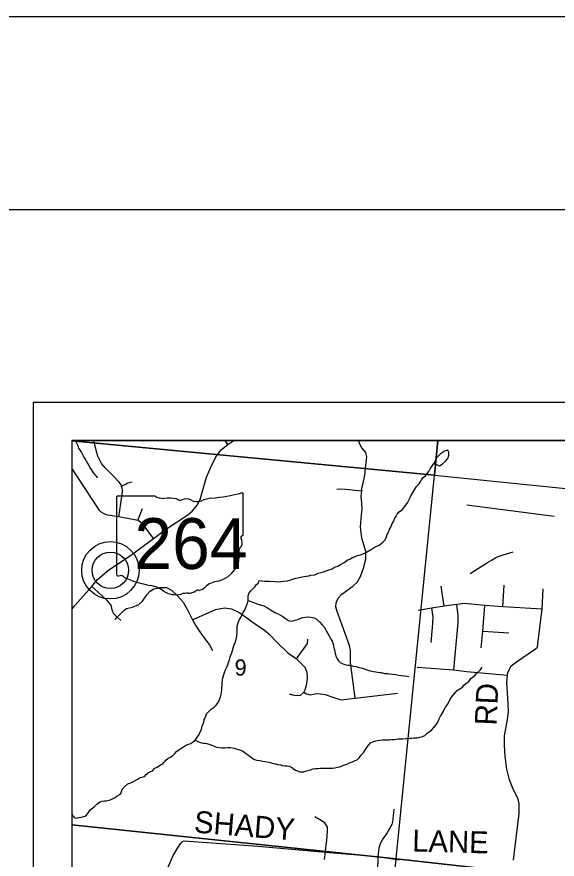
# Model space of a CAD drawing. Extents: x 0 to 43.4, y -8.1 to 22.
# Drawn here: x 1.957 to 3.361, y 19.813 to 22 of the extents above; entities that cross this region are included whole.
import ezdxf

# ---------------------------------------------------------------- set-up
doc = ezdxf.new("R2010")
doc.units = 0
for name, color, linetype in [('GM_X_Corporation', 7, 'Continuous'), ('GM_X_County_Road', 7, 'Continuous'), ('GM_X_County_Road_Text', 7, 'Continuous'), ('GM_X_Minor_Lake', 7, 'Continuous'), ('GM_X_Minor_River', 7, 'Continuous'), ('GM_X_Section_Text', 7, 'Continuous'), ('GM_X_State_Location', 7, 'Continuous'), ('GM_X_State_Route', 7, 'Continuous'), ('GM_X_State_Shield', 7, 'Continuous'), ('GM_X_Township_Road', 7, 'Continuous'), ('GM_X_Unincorporated', 7, 'Continuous'), ('GM_X_Unincorporated_Location', 7, 'Continuous'), ('SH_Border', 7, 'Continuous'), ('SH_Cut_Line', 7, 'Continuous'), ('SH_Data', 7, 'Continuous')]:
    doc.layers.add(name, color=color, linetype=linetype)

msp = doc.modelspace()

# ---------------------------------------------------------------- linework, layer by layer
at = {"layer": 'GM_X_Corporation'}
for points in [[(8.9, 20.9), (2.1, 20.9), (2.1, 18.7697), (2.2164, 18.6602), (2.3024, 18.5637), (2.4531, 18.3722), (2.5091, 18.2757), (2.5944, 18.1569), (2.6477, 18.0826), (2.8129, 17.7895), (2.9482, 17.5993), (3.2529, 17.1207), (3.3535, 16.9292), (3.4766, 16.7366), (3.5579, 16.6418), (3.619, 16.5459), (3.7774, 16.2543), (3.8686, 16.1561), (3.9643, 16.0791), (4.2564, 15.9373), (4.3533, 15.9108)], [(3.918, 19.4441), (3.9936, 20.1953), (4.0006, 20.2658), (4.0111, 20.3696), (4.0645, 20.9), (2.1, 20.9), (2.1, 18.7697)]]:
    msp.add_lwpolyline(points, dxfattribs=at)
for points in [[(3.0509, 20.9), (2.1, 20.9), (2.1, 20.8994), (3.042, 20.8098)], [(2.1, 20.8994), (2.1, 19.9021), (2.9428, 19.8144), (3.042, 20.8098)], [(4.0674, 20.9), (3.0509, 20.9), (3.042, 20.8098), (4.0476, 20.7082)], [(4.0476, 20.7082), (3.9403, 19.703), (2.9428, 19.8144), (3.042, 20.8098)], [(2.1, 19.9021), (2.1, 18.897), (2.8429, 18.8166), (2.9428, 19.8144)], [(2.9428, 19.8144), (3.9403, 19.703), (3.8378, 18.6959), (2.8429, 18.8166)]]:
    msp.add_lwpolyline(points, close=True, dxfattribs=at)
at = {"layer": 'GM_X_County_Road'}
for points in [[(3.2479, 19.8108), (3.2621, 19.9316), (3.2624, 19.9576), (3.2602, 19.9693), (3.245, 19.9994), (3.237, 20.0194), (3.2307, 20.0466), (3.226, 20.0798), (3.2241, 20.1093), (3.224, 20.1332), (3.2284, 20.1566), (3.2324, 20.1755), (3.2344, 20.1964), (3.2335, 20.2158), (3.2317, 20.2451), (3.2301, 20.2706), (3.2314, 20.282), (3.2322, 20.2908), (3.2333, 20.2971), (3.2362, 20.3051), (3.242, 20.315), (3.2554, 20.3258), (3.3049, 20.3594), (3.31, 20.3635), (3.3119, 20.3801), (3.3218, 20.4625), (3.3246, 20.515)], [(2.3455, 19.7799), (2.363, 19.8224), (2.3734, 19.8403), (2.3829, 19.8545), (2.3872, 19.859), (2.3922, 19.8611), (2.5831, 19.8466), (2.759, 19.8311), (2.8955, 19.8202), (2.9503, 19.8114)]]:
    msp.add_lwpolyline(points, dxfattribs=at)
at = {"layer": 'GM_X_Minor_Lake'}
for points in [[(3.041, 20.84), (3.0558, 20.8343), (3.0624, 20.8387), (3.071, 20.8464), (3.0773, 20.8535), (3.0798, 20.8621), (3.0796, 20.8694), (3.0771, 20.8751), (3.0686, 20.8723), (3.0578, 20.8654), (3.0492, 20.8572)], [(3.0492, 20.8572), (3.0457, 20.8532), (3.0432, 20.8445), (3.041, 20.84)]]:
    msp.add_lwpolyline(points, dxfattribs=at)
at = {"layer": 'GM_X_Minor_River'}
for points in [[(2.1089, 20.9), (2.1124, 20.8942), (2.1155, 20.8869), (2.1176, 20.8803), (2.1216, 20.8741), (2.1252, 20.8687), (2.1277, 20.8636), (2.1312, 20.8567), (2.1348, 20.8516), (2.138, 20.8454), (2.1413, 20.8396), (2.1441, 20.8349), (2.1488, 20.8272), (2.1575, 20.8147), (2.1615, 20.8096), (2.1655, 20.8038), (2.1661, 20.8028)], [(2.6008, 20.5352), (2.6053, 20.5347), (2.6133, 20.5348), (2.6273, 20.5343), (2.6383, 20.5335), (2.6429, 20.5338), (2.6501, 20.5347), (2.6604, 20.5362), (2.6669, 20.5375), (2.6742, 20.5399), (2.6819, 20.5427), (2.6869, 20.5436), (2.6987, 20.5459), (2.704, 20.5469), (2.7094, 20.5478), (2.7159, 20.5491), (2.7209, 20.5504), (2.7312, 20.5516), (2.7404, 20.5555), (2.7481, 20.5571), (2.7592, 20.5613), (2.7654, 20.5637), (2.7761, 20.5672), (2.7846, 20.5722), (2.7908, 20.5739), (2.7978, 20.5778), (2.8094, 20.5843), (2.816, 20.5901), (2.821, 20.5914), (2.8295, 20.5961), (2.8341, 20.5982), (2.8399, 20.6011), (2.8457, 20.6028), (2.8529, 20.604), (2.8591, 20.6068), (2.8653, 20.6104), (2.87, 20.6129), (2.8808, 20.6186), (2.8855, 20.6223), (2.8909, 20.6251), (2.8982, 20.6283), (2.9029, 20.6316), (2.9087, 20.6367), (2.9146, 20.6422), (2.9179, 20.65), (2.9196, 20.6557), (2.9217, 20.6605), (2.9242, 20.6654), (2.9258, 20.6699), (2.9287, 20.6751), (2.9303, 20.6796), (2.9324, 20.6849), (2.9356, 20.6897), (2.9377, 20.6942), (2.9393, 20.6987), (2.9425, 20.7035), (2.9458, 20.7087), (2.9505, 20.715), (2.9595, 20.7212), (2.9643, 20.7279), (2.9682, 20.7323), (2.9718, 20.7379), (2.9747, 20.7431), (2.9788, 20.7521), (2.9816, 20.758), (2.9864, 20.7651), (2.9909, 20.7741), (2.9953, 20.7804), (3.0024, 20.7873), (3.0052, 20.7918), (3.0084, 20.7978), (3.0132, 20.8037), (3.0194, 20.8084), (3.0227, 20.814), (3.0278, 20.8199), (3.0314, 20.8262), (3.0371, 20.8355), (3.041, 20.84)], [(2.5294, 20.413), (2.5295, 20.4184), (2.5312, 20.424), (2.5333, 20.4292), (2.5358, 20.4352), (2.5399, 20.4423), (2.5424, 20.4487), (2.5456, 20.4539), (2.5484, 20.4591), (2.5521, 20.4662), (2.5546, 20.4734), (2.5575, 20.4801), (2.558, 20.4846), (2.5579, 20.4915), (2.5584, 20.4972), (2.561, 20.5043), (2.5658, 20.511), (2.5716, 20.5157), (2.576, 20.5209), (2.5788, 20.5253), (2.5846, 20.5301), (2.5872, 20.5368), (2.6008, 20.5352)], [(2.558, 20.485), (2.573, 20.4792), (2.5775, 20.4779), (2.5835, 20.475), (2.5925, 20.4728), (2.5985, 20.4707), (2.6086, 20.4658), (2.6164, 20.4606), (2.625, 20.455), (2.6294, 20.4529), (2.6358, 20.45), (2.6485, 20.4435), (2.6551, 20.4383), (2.6633, 20.4331), (2.6701, 20.431), (2.6754, 20.4315), (2.6804, 20.4337), (2.6869, 20.4353), (2.6923, 20.4378), (2.7004, 20.4402), (2.7076, 20.4418), (2.7156, 20.4419), (2.7254, 20.4405), (2.73, 20.4399), (2.7355, 20.4363), (2.7444, 20.4288), (2.7502, 20.4217), (2.7572, 20.4143), (2.7589, 20.4097), (2.7614, 20.4042), (2.7661, 20.3969), (2.77, 20.3891), (2.7732, 20.3845), (2.7761, 20.379), (2.7789, 20.3721), (2.7798, 20.3664), (2.7808, 20.3614), (2.7835, 20.3529), (2.7845, 20.3468), (2.7868, 20.3384), (2.7893, 20.3333), (2.7926, 20.3283), (2.7973, 20.3236), (2.8026, 20.3215), (2.8071, 20.3198), (2.8116, 20.3181), (2.8169, 20.3172), (2.8229, 20.3166), (2.8286, 20.3153), (2.8331, 20.3143), (2.8391, 20.313), (2.8436, 20.3117), (2.8508, 20.3096), (2.8606, 20.3073), (2.8658, 20.3049), (2.8748, 20.3023), (2.8797, 20.3009), (2.8842, 20.3), (2.8899, 20.2991), (2.8982, 20.298), (2.9035, 20.2975), (2.9125, 20.2956), (2.9209, 20.295), (2.9258, 20.294), (2.933, 20.2934), (2.9409, 20.2924), (2.9492, 20.2913), (2.9564, 20.2899), (2.9647, 20.2889), (2.9711, 20.2879), (2.976, 20.2874)], [(2.1, 19.9302), (2.1029, 19.9257), (2.1073, 19.9206), (2.1125, 19.9197), (2.1175, 19.9214), (2.1236, 19.9223), (2.129, 19.9229), (2.1336, 19.9247), (2.1383, 19.9275), (2.1431, 19.9346), (2.1478, 19.9413), (2.158, 19.9489), (2.1643, 19.9555), (2.169, 19.9592), (2.1736, 19.962), (2.1786, 19.9634), (2.1847, 19.9643), (2.19, 19.9649), (2.1977, 19.9662), (2.2038, 19.969), (2.2127, 19.9732), (2.2174, 19.9765), (2.2225, 19.9801), (2.2271, 19.9838), (2.2288, 19.9886), (2.2317, 19.9961), (2.2372, 20.0013), (2.2455, 20.0086), (2.2508, 20.0107), (2.2582, 20.0142), (2.2648, 20.0178), (2.2713, 20.0206), (2.276, 20.0246), (2.2886, 20.028), (2.293, 20.0332), (2.2988, 20.0371), (2.3054, 20.0411), (2.31, 20.0428), (2.316, 20.0491), (2.3214, 20.0523), (2.3307, 20.0581), (2.3365, 20.0606), (2.3444, 20.0698), (2.3495, 20.0742), (2.3564, 20.0781), (2.3631, 20.0836), (2.3681, 20.0872), (2.3721, 20.0924), (2.3834, 20.1004), (2.3904, 20.1051), (2.3978, 20.1097), (2.4032, 20.1118), (2.4093, 20.1135), (2.414, 20.1172), (2.4186, 20.12), (2.4234, 20.1252), (2.4266, 20.1308), (2.431, 20.1371), (2.4339, 20.1438), (2.4368, 20.1502), (2.4389, 20.1585), (2.4411, 20.1649), (2.4427, 20.1698), (2.4437, 20.1754), (2.4461, 20.1799), (2.4478, 20.1844), (2.4503, 20.1908), (2.457, 20.1974), (2.4621, 20.2025), (2.4699, 20.208), (2.4754, 20.2131), (2.4789, 20.2175), (2.4822, 20.2235), (2.4839, 20.228), (2.4864, 20.2344), (2.489, 20.2449), (2.4897, 20.2536), (2.4899, 20.2586), (2.4904, 20.2646), (2.491, 20.2707), (2.4916, 20.2771), (2.4926, 20.2843), (2.4944, 20.2904), (2.4969, 20.2982), (2.4994, 20.305), (2.5031, 20.3117), (2.5052, 20.3181), (2.5073, 20.3237), (2.5094, 20.3305), (2.5112, 20.3373), (2.5136, 20.3425), (2.5157, 20.3485), (2.5179, 20.3553), (2.5213, 20.3666), (2.5263, 20.3801), (2.529, 20.3922), (2.5294, 20.4047), (2.5294, 20.413)], [(3.076, 20.2147), (3.0793, 20.2211), (3.0825, 20.227), (3.0862, 20.2334), (3.0897, 20.2378), (3.0953, 20.2441), (3.1016, 20.2507), (3.1082, 20.2558), (3.1155, 20.2597), (3.1188, 20.2646), (3.1238, 20.2689), (3.1312, 20.2744), (3.1368, 20.2818), (3.147, 20.2902), (3.1529, 20.2972), (3.1607, 20.3041), (3.1666, 20.3118)], [(2.4207, 20.1223), (2.4292, 20.1182), (2.4341, 20.1161), (2.4401, 20.1147), (2.4465, 20.1141), (2.451, 20.1132), (2.4559, 20.1115), (2.4638, 20.109), (2.4713, 20.1057), (2.4758, 20.104), (2.4837, 20.103), (2.4902, 20.1024), (2.4974, 20.1025), (2.5054, 20.103), (2.5122, 20.1031), (2.5216, 20.1013), (2.5269, 20.0999), (2.5333, 20.0978), (2.5438, 20.094), (2.5512, 20.0885), (2.5564, 20.0852), (2.5638, 20.0793), (2.5701, 20.0749), (2.5745, 20.0721), (2.5809, 20.0703), (2.5873, 20.069), (2.596, 20.0679), (2.6013, 20.0666), (2.6066, 20.0656), (2.6122, 20.0647), (2.6205, 20.0625), (2.6299, 20.0603), (2.6352, 20.0589), (2.642, 20.058), (2.6477, 20.0566), (2.6544, 20.0556), (2.6594, 20.0551), (2.6639, 20.0549), (2.671, 20.0516), (2.6755, 20.0488), (2.6814, 20.044), (2.6923, 20.0402), (2.6968, 20.0397), (2.7025, 20.0403), (2.7075, 20.042), (2.7205, 20.045), (2.7274, 20.0474), (2.7332, 20.0483), (2.7389, 20.0489), (2.7457, 20.0494), (2.7548, 20.0491), (2.7704, 20.0493), (2.7772, 20.0495), (2.7833, 20.0504), (2.7902, 20.0517), (2.799, 20.054), (2.8056, 20.0572), (2.8152, 20.0599), (2.8218, 20.0635), (2.8294, 20.0659), (2.8341, 20.0684), (2.8426, 20.0719), (2.8469, 20.0763), (2.8509, 20.0823), (2.8588, 20.0907), (2.866, 20.1019), (2.8716, 20.1104), (2.8763, 20.1152), (2.884, 20.1184), (2.8902, 20.1208), (2.9005, 20.1224), (2.9073, 20.1229), (2.9134, 20.123), (2.9256, 20.123), (2.9305, 20.1236), (2.9381, 20.1241), (2.9427, 20.1247), (2.9477, 20.1253), (2.9537, 20.1255), (2.9602, 20.1256), (2.9682, 20.1265), (2.9728, 20.1267), (2.9781, 20.1269), (2.9838, 20.1275), (2.9888, 20.128), (2.9979, 20.1285), (3.004, 20.1298), (3.0113, 20.1318), (3.0174, 20.1339), (3.0226, 20.1394), (3.0354, 20.1492), (3.0398, 20.1544), (3.0453, 20.1599), (3.0505, 20.1673), (3.0542, 20.1775), (3.0579, 20.1846), (3.0627, 20.1912), (3.0648, 20.1961), (3.0676, 20.2013), (3.0709, 20.2081), (3.076, 20.2147)]]:
    msp.add_lwpolyline(points, dxfattribs=at)
at = {"layer": 'GM_X_State_Route'}
msp.add_lwpolyline([(2.1, 20.4615), (2.1077, 20.4715), (2.1522, 20.5213), (2.1669, 20.539), (2.1962, 20.5641), (2.2522, 20.6012), (2.3124, 20.6454), (2.3433, 20.6687), (2.4012, 20.7075), (2.4129, 20.7167), (2.419, 20.7235), (2.426, 20.7326), (2.4331, 20.7466), (2.4376, 20.7626), (2.45, 20.8048), (2.4624, 20.833), (2.4741, 20.8577), (2.4887, 20.8764), (2.5056, 20.8897), (2.5213, 20.9)], dxfattribs=at)
at = {"layer": 'GM_X_State_Shield'}
for p, q in [((2.3157, 20.756), (2.2192, 20.756)), ((2.5455, 20.6563), (2.5455, 20.761)), ((2.216, 20.7526), (2.216, 20.5525)), ((2.5455, 20.6563), (2.5455, 20.6563))]:
    msp.add_line(p, q, dxfattribs=at)
for centre, major_axis, start_param, end_param in [((2.2197, 20.753), (0.00382, 0), 1.712693, 3.28349), ((2.3387, 20.7793), (0.037, 0), 4.042523, 4.731795), ((2.4281, 21.0289), (0.3495, 0), 4.814394, 5.042369), ((2.5419, 20.7614), (0.00367, 0), 6.141152, 7.989035), ((2.351, 20.6437), (0.133, 0), 1.404758, 1.657858), ((2.3812, 20.754), (0.0107, 0), 3.836095, 5.185415), ((2.3968, 20.7309), (0.0222, 0), 0.950623, 2.079405), ((2.4255, 20.7626), (0.0267, 0), 4.081561, 5.145723), ((2.4727, 20.6949), (0.0703, 0), 1.699011, 2.107814), ((2.5447, 20.6486), (0.00568, 0), 1.883978, 3.671073), ((2.5086, 20.6354), (0.0341, 0), 5.934695, 6.695948), ((2.5416, 20.6559), (0.00393, 0), 5.05454, 6.418171), ((2.5587, 20.6125), (0.0248, 0), 2.387724, 3.262537), ((2.4477, 20.5992), (0.0874, 0), 5.101752, 6.440018), ((2.2198, 20.552), (0.00385, 0), 3.00124, 4.508301), ((2.2203, 20.5725), (0.0294, 0), 4.665946, 4.897461), ((2.2264, 20.5409), (0.0106, 0), 0.519207, 1.627899), ((2.3602, 20.7207), (0.2524, 0), 4.195997, 4.488961), ((2.4846, 20.4963), (0.0479, 0), 1.647645, 2.488434), ((2.2849, 20.4626), (0.079, 0), 0.823519, 1.323587), ((2.4239, 20.5331), (0.0282, 0), 4.937069, 5.64225), ((2.3703, 20.5399), (0.0501, 0), 4.026481, 4.996735), ((2.3993, 20.4707), (0.0412, 0), 1.495662, 1.94098), ((2.403, 20.5249), (0.0267, 0), 4.691044, 5.507374), ((2.4271, 20.5056), (0.00752, 0), 1.147584, 2.315152)]:
    msp.add_ellipse(centre, major_axis=major_axis, ratio=0.8, start_param=start_param, end_param=end_param, dxfattribs=at)
at = {"layer": 'GM_X_Township_Road'}
for p, q in [((2.5056, 20.8897), (2.4987, 20.9)), ((3.3535, 20.7029), (3.1266, 20.7322)), ((2.2719, 20.692), (2.284, 20.7235)), ((3.0672, 20.4702), (3.0596, 20.5216)), ((3.2196, 20.4687), (3.223, 20.5248)), ((3.1683, 20.4055), (3.2358, 20.4011))]:
    msp.add_line(p, q, dxfattribs=at)
for points in [[(2.2291, 20.7819), (2.2283, 20.7846), (2.226, 20.7885), (2.2219, 20.7929), (2.2083, 20.8073), (2.195, 20.8205), (2.1867, 20.8292), (2.1811, 20.8351), (2.1772, 20.8405), (2.1745, 20.8457), (2.1707, 20.8524), (2.1678, 20.8596), (2.1636, 20.8746), (2.1569, 20.9)], [(2.8362, 20.2313), (2.8239, 20.3239), (2.8239, 20.3402), (2.8239, 20.3539), (2.8218, 20.3676), (2.7989, 20.4306), (2.7892, 20.4561), (2.7859, 20.4679), (2.7868, 20.4783), (2.7918, 20.4908), (2.8017, 20.5008), (2.83, 20.5218), (2.8423, 20.5333), (2.8504, 20.5468), (2.8579, 20.5688), (2.8638, 20.5922), (2.8636, 20.6115), (2.8593, 20.6269), (2.8539, 20.6469), (2.8518, 20.6604), (2.8504, 20.6758), (2.8529, 20.7074), (2.8544, 20.7211), (2.8539, 20.7374), (2.8518, 20.7556), (2.8532, 20.7693), (2.8539, 20.7761), (2.8574, 20.7894), (2.8615, 20.8099), (2.8631, 20.8288), (2.8652, 20.8425), (2.8657, 20.8503), (2.8664, 20.8571), (2.8638, 20.8687), (2.8532, 20.8812), (2.847, 20.8937), (2.8463, 20.9)], [(2.3124, 20.6454), (2.2876, 20.679), (2.2831, 20.6843), (2.2788, 20.6878), (2.2749, 20.6907), (2.2719, 20.692), (2.2674, 20.6936), (2.2218, 20.7018), (2.1934, 20.7063), (2.1875, 20.7082), (2.182, 20.7106), (2.1764, 20.7143), (2.1721, 20.7183), (2.1674, 20.7252), (2.1, 20.8286)], [(2.2218, 20.7018), (2.2275, 20.7366), (2.2291, 20.7485), (2.2311, 20.7612), (2.2317, 20.7671), (2.2315, 20.772), (2.2309, 20.7756), (2.2295, 20.7803), (2.2291, 20.7819)], [(2.2291, 20.7819), (2.2358, 20.785), (2.2409, 20.7877), (2.2456, 20.79), (2.2487, 20.7913), (2.2521, 20.7922), (2.2568, 20.7929)], [(2.7887, 20.7741), (2.797, 20.7744), (2.8111, 20.7736), (2.8532, 20.7693)], [(3.1352, 20.555), (3.1804, 20.5834), (3.192, 20.5907), (3.2039, 20.5969), (3.2208, 20.6033), (3.2465, 20.6113)], [(2.2278, 20.4327), (2.2178, 20.4418), (2.2095, 20.45), (2.206, 20.4573), (2.202, 20.4722), (2.193, 20.4837), (2.1697, 20.5059), (2.1522, 20.5213)], [(2.2124, 20.4355), (2.2178, 20.4418), (2.237, 20.4609), (2.2425, 20.4636), (2.2579, 20.4673), (2.2743, 20.4745), (2.2837, 20.4831), (2.2951, 20.4996), (2.304, 20.509), (2.3135, 20.5147), (2.3291, 20.5185), (2.3456, 20.5185), (2.3593, 20.5112), (2.3749, 20.4972), (2.3897, 20.4802), (2.4013, 20.4585), (2.4075, 20.4467), (2.4135, 20.4347), (2.4225, 20.4189), (2.4324, 20.4031), (2.4481, 20.382), (2.4581, 20.3693), (2.4657, 20.355)], [(3.3218, 20.4625), (3.2196, 20.4687), (3.1734, 20.4715), (3.1201, 20.4769), (3.1, 20.4745), (3.0672, 20.4702), (3.0351, 20.4646), (3.0002, 20.4591)], [(3.0929, 20.3043), (3.1039, 20.4272), (3.1041, 20.4458), (3.1, 20.4745)], [(3.1633, 20.3619), (3.1683, 20.4055), (3.1734, 20.4715)], [(2.4135, 20.4347), (2.4732, 20.4616), (2.4963, 20.4653), (2.5148, 20.4634), (2.537, 20.4531), (2.5799, 20.4214), (2.6001, 20.4082), (2.6124, 20.3972), (2.6333, 20.3756), (2.6614, 20.349), (2.6838, 20.3337), (2.7051, 20.3113), (2.7103, 20.2986), (2.7113, 20.2825), (2.7088, 20.264), (2.7056, 20.2518), (2.7025, 20.2464), (2.6933, 20.2381), (2.6829, 20.2374), (2.674, 20.2387), (2.6655, 20.2416)], [(3.0337, 20.3756), (3.0375, 20.4144), (3.0383, 20.427), (3.0385, 20.4419), (3.0351, 20.4646)], [(2.6838, 20.3337), (2.712, 20.3731), (2.713, 20.3841)], [(2.9973, 20.312), (3.0929, 20.3043), (3.1126, 20.3022)], [(3.1126, 20.3022), (3.1254, 20.3008), (3.2322, 20.2908)], [(2.7025, 20.2464), (2.7094, 20.2422), (2.719, 20.2398), (2.7327, 20.2422), (2.7394, 20.2433), (2.7587, 20.2403), (2.7783, 20.2337), (2.7915, 20.2294), (2.8001, 20.2268), (2.8362, 20.2313), (2.9462, 20.2443)], [(2.7567, 19.8127), (2.759, 19.8311), (2.7598, 19.8423), (2.7625, 19.8629), (2.7646, 19.8855), (2.7643, 19.896), (2.7573, 19.9072), (2.7318, 19.9229)], [(2.9369, 19.9434), (2.9342, 19.9171), (2.9336, 19.9105), (2.9311, 19.9029), (2.9244, 19.8911), (2.9192, 19.8818), (2.9085, 19.8663), (2.9009, 19.853), (2.8974, 19.8414), (2.8955, 19.8202), (2.8935, 19.7469)]]:
    msp.add_lwpolyline(points, dxfattribs=at)
at = {"layer": 'GM_X_Unincorporated'}
for radius in [0.0744, 0.0472]:
    msp.add_circle((2.2002, 20.5631), radius, dxfattribs=at)
at = {"layer": 'GM_X_Unincorporated_Location'}
msp.add_line((2.2002, 20.5631), (2.2002, 20.5631), dxfattribs=at)
at = {"layer": 'SH_Border'}
msp.add_lwpolyline([(1.5, 21.5), (33.5, 21.5), (33.5, 0.5), (1.5, 0.5)], close=True, dxfattribs=at)
at = {"layer": 'SH_Cut_Line'}
msp.add_lwpolyline([(0, 0), (34, 0), (34, 22), (0, 22)], close=True, dxfattribs=at)
at = {"layer": 'SH_Data'}
for p, q in [((2, 21), (9, 21)), ((2, 21), (2, 14)), ((2.1, 20.9), (2.1, 14.1)), ((2.1, 20.9), (8.9, 20.9))]:
    msp.add_line(p, q, dxfattribs=at)

# ---------------------------------------------------------------- texts
at = {"layer": 'GM_X_County_Road_Text'}
for s, rotation, p in [('RD', 87.5318, (3.2037, 20.1595)), ('SHADY', 355.4176, (2.4161, 19.8825)), ('LANE', 358.4524, (2.984, 19.8333))]:
    msp.add_text(s, height=0.05682, rotation=rotation, dxfattribs=at).set_placement(p)
at = {"layer": 'GM_X_Section_Text'}
msp.add_text('9', height=0.0419, rotation=0, dxfattribs=at).set_placement((2.5231, 20.2898))
at = {"layer": 'GM_X_State_Location'}
msp.add_text('264', height=0.000189, rotation=0, dxfattribs=at).set_placement((2.3102, 20.6254))
for s in ['s', 'r']:
    msp.add_text(s, height=0.000189, dxfattribs=at).set_placement((2.377, 20.6392))
at = {"layer": 'GM_X_State_Shield'}
msp.add_text('264', height=0.13184, dxfattribs=at).set_placement((2.2625, 20.5666))

doc.saveas('drawing.dxf')
